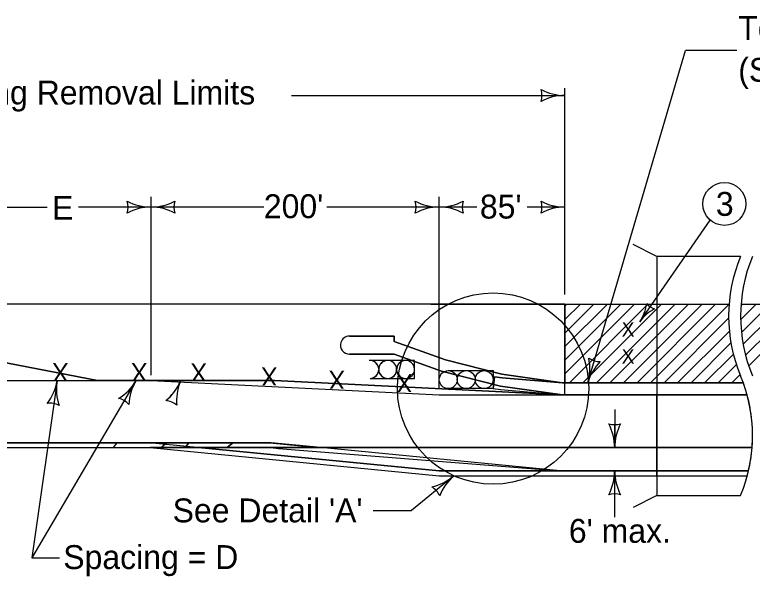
# Model space of a CAD drawing. Extents: x 10133 to 2270741, y 5363 to 1733450.
# Drawn here: x 26474 to 27091, y 6564 to 7034 of the extents above; entities that cross this region are included whole.
import ezdxf

# ---------------------------------------------------------------- set-up
doc = ezdxf.new("R2010")
doc.units = 0
for name, color, linetype in [('dsnNonPlotable', 7, 'Continuous'), ('dsnShtPlotShapeBatchPrint', 7, 'Continuous'), ('dsnStdBlockModified', 7, 'Continuous'), ('dsnStdBorder', 7, 'Continuous'), ('Level 12', 7, 'Continuous'), ('Level 2', 7, 'Continuous')]:
    doc.layers.add(name, color=color, linetype=linetype)

# ---------------------------------------------------------------- blocks, each defined once
blk = doc.blocks.new('LT')
at = {"layer": 'dsnStdBorder'}
for centre, radius, start, end in [((-3.564, 0), 1.642, 342.26665, 17.73335), ((0, 4.25), 4.25, 241.92751, 270), ((0, -4.25), 4.25, 90, 118.07249)]:
    blk.add_arc(centre, radius, start, end, dxfattribs=at)

msp = doc.modelspace()

# ---------------------------------------------------------------- linework, layer by layer
at = {"layer": 'dsnNonPlotable'}
for p, q in [((27011.27, 6831.83), (26991.27, 6841.83)), ((26439.83, 6728.09), (26588.02, 6728.09)), ((26588.02, 6728.09), (26829.07, 6716.09)), ((26932.38, 6726.09), (27083.5, 6726.09)), ((26829.07, 6716.09), (26932.38, 6716.09)), ((27086.67, 6716.09), (26932.38, 6716.09)), ((24557.83, 6675.81), (26586.2, 6675.81)), ((26587.39, 6671.83), (26913.23, 6671.83)), ((26913.23, 6671.83), (27090.89, 6671.83)), ((26829.07, 6652.32), (27087.88, 6652.32)), ((27011.27, 6631.83), (26991.27, 6621.83))]:
    msp.add_line(p, q, dxfattribs=at)
for points in [[(27081.27, 6831.83), (27011.27, 6831.83), (27011.27, 6631.83), (27081.27, 6631.83)], [(26875.5, 6731.07), (26874.23, 6721.23), (26874.23, 6721.23)], [(26875.5, 6731.07), (26881.73, 6730.26), (26932.38, 6726.09)], [(26874.23, 6721.23), (26880.46, 6720.42), (26932.38, 6716.09)]]:
    msp.add_lwpolyline(points, dxfattribs=at)
for centre, start, end in [((27201.27, 6781.83), 157.38014, 202.61987), ((27211.27, 6781.83), 157.38014, 202.61987), ((26961.27, 6681.83), 337.38014, 22.61987)]:
    msp.add_arc(centre, 130, start, end, dxfattribs=at)
at = {"layer": 'dsnShtPlotShapeBatchPrint'}
msp.add_circle((27067.71, 6875.77), 18, dxfattribs=at)
at = {"layer": 'dsnStdBlockModified'}
for p, q in [((26836.72, 6736.23), (26874.23, 6736.23)), ((26874.23, 6736.23), (26874.23, 6721.23)), ((26874.23, 6721.23), (26836.72, 6721.23))]:
    msp.add_line(p, q, dxfattribs=at)
for centre in [(26836.72, 6728.73), (26836.72, 6728.73), (26851.73, 6728.73), (26851.73, 6728.73), (26866.73, 6728.73), (26866.73, 6728.73)]:
    msp.add_circle(centre, 7.5, dxfattribs=at)
at = {"layer": 'dsnStdBorder'}
for p, q in [((26934.34, 6790.27), (26935.89, 6791.83)), ((26934.34, 6778.95), (26947.21, 6791.83)), ((26934.34, 6767.64), (26958.52, 6791.83)), ((26934.34, 6756.33), (26969.84, 6791.83)), ((26934.34, 6745.01), (26981.15, 6791.83)), ((26934.34, 6733.7), (26992.46, 6791.83)), ((26934.34, 6791.83), (26934.34, 6726.09)), ((26938.04, 6726.09), (27003.78, 6791.83)), ((26949.36, 6726.09), (27015.09, 6791.83)), ((26960.67, 6726.09), (27026.4, 6791.83)), ((26971.98, 6726.09), (27037.72, 6791.83)), ((26983.3, 6726.09), (27049.03, 6791.83)), ((26994.61, 6726.09), (27060.34, 6791.83)), ((27045.11, 6787.86), (27049.07, 6791.83)), ((27045.89, 6766.06), (27071.66, 6791.83)), ((27081.31, 6778.85), (27094.29, 6791.83)), ((27081.56, 6790.41), (27082.97, 6791.83)), ((27081.99, 6768.21), (27105.6, 6791.83)), ((27083.41, 6758.33), (27116.91, 6791.83)), ((27085.47, 6749.07), (27128.23, 6791.83)), ((27088.07, 6740.35), (27139.54, 6791.83)), ((27017.24, 6726.09), (27071.28, 6780.14)), ((27028.55, 6726.09), (27071.87, 6769.41)), ((27005.92, 6726.09), (27045.89, 6766.06)), ((27039.87, 6726.09), (27073.21, 6759.44)), ((27051.18, 6726.09), (27075.2, 6750.12)), ((27062.49, 6726.09), (27077.74, 6741.34)), ((27073.81, 6726.09), (27080.77, 6733.05)), ((26829.07, 6652.32), (26586.2, 6675.81))]:
    msp.add_line(p, q, dxfattribs=at)
for centre, radius in [((26874.23, 6721.23), 80), ((26836.72, 6728.73), 7.5), ((26851.73, 6728.73), 7.5), ((26866.73, 6728.73), 7.5)]:
    msp.add_circle(centre, radius, dxfattribs=at)
at = {"layer": 'Level 12'}
for p, q in [((26953.42, 6726.09), (27035.19, 7004.13)), ((27078.03, 7004.13), (27035.19, 7004.13)), ((26934.34, 6799.83), (26934.34, 6972.59)), ((26705.58, 6966.53), (26934.34, 6966.53)), ((26588.02, 6732.52), (26588.02, 6881.62)), ((26829.07, 6720.64), (26829.07, 6881.62)), ((26384.24, 6873.11), (26501.08, 6873.11)), ((26682.49, 6873.11), (26527.28, 6873.11)), ((26829.07, 6873.11), (26735.18, 6873.11)), ((26860.64, 6873.11), (26829.07, 6873.11)), ((26934.34, 6873.11), (26902.77, 6873.11)), ((26996.87, 6777.1), (27055.83, 6862.25)), ((26509.43, 6727.69), (26488.2, 6579.64)), ((26575.4, 6727.69), (26488.2, 6579.64)), ((26975.92, 6703.83), (26975.92, 6671.83)), ((26965.1, 6671.83), (26983.92, 6671.83)), ((26966.11, 6652.32), (26983.92, 6652.32)), ((26975.92, 6613.56), (26975.92, 6652.32)), ((26841.33, 6648.31), (26805.99, 6619.1)), ((26773.99, 6619.1), (26805.99, 6619.1)), ((26488.2, 6579.64), (26511.33, 6579.64))]:
    msp.add_line(p, q, dxfattribs=at)
for centre, radius, start, end in [((26898.7, 6966.53), 16.42, 342.26665, 17.73335), ((26934.34, 7009.03), 42.5, 241.92751, 270), ((26934.34, 6924.03), 42.5, 90, 118.07249), ((26552.38, 6873.11), 16.42, 342.26665, 17.73335), ((26588.02, 6915.61), 42.5, 241.92751, 270), ((26588.02, 6915.61), 42.5, 270, 298.07249), ((26623.65, 6873.11), 16.42, 162.26665, 197.73335), ((26793.43, 6873.11), 16.42, 342.26665, 17.73335), ((26829.07, 6915.61), 42.5, 241.92751, 270), ((26829.07, 6915.61), 42.5, 270, 298.07249), ((26864.71, 6873.11), 16.42, 162.26665, 197.73335), ((26898.7, 6873.11), 16.42, 342.26665, 17.73335), ((26934.34, 6915.61), 42.5, 241.92751, 270), ((26588.02, 6830.61), 42.5, 90, 118.07249), ((26588.02, 6830.61), 42.5, 61.92751, 90), ((26829.07, 6830.61), 42.5, 90, 118.07249), ((26829.07, 6830.61), 42.5, 61.92751, 90), ((26934.34, 6830.61), 42.5, 90, 118.07249), ((26912.65, 6738.08), 42.5, 343.61306, 11.68555), ((26994.2, 6714.1), 42.5, 135.54057, 163.61306), ((26963.48, 6760.28), 16.42, 235.87971, 271.34641), ((26467.49, 6734.6), 42.5, 322.56873, 350.64122), ((26551.36, 6720.78), 42.5, 170.64122, 198.71371), ((26538.78, 6749.25), 42.5, 301.43193, 329.50442), ((26612.02, 6706.12), 42.5, 149.50442, 177.57691), ((26557.31, 6696.98), 16.42, 41.77107, 77.23777), ((26503.63, 6692.53), 16.42, 62.90787, 98.37457), ((26975.92, 6707.46), 16.42, 252.26665, 287.73335), ((26933.42, 6671.83), 42.5, 360, 28.07249), ((27018.42, 6671.83), 42.5, 151.92751, 180), ((26933.42, 6652.32), 42.5, 331.92751, 360), ((27018.42, 6652.32), 42.5, 180, 208.07249), ((26813.42, 6680.36), 42.5, 282.97403, 311.04652), ((26869.24, 6616.25), 42.5, 131.04652, 159.11901), ((26814.45, 6624.91), 16.42, 23.31317, 58.77987), ((26975.92, 6616.69), 16.42, 72.26665, 107.73335)]:
    msp.add_arc(centre, radius, start, end, dxfattribs=at)
at = {"layer": 'Level 2'}
for p, q in [((26822.2, 6791.83), (25991.54, 6791.83)), ((26822.2, 6791.83), (27071.66, 6791.83)), ((27081.66, 6791.83), (27600.09, 6791.83)), ((26934.34, 6767.64), (26934.34, 6778.95)), ((26791.49, 6760.74), (26791.49, 6765.11)), ((26768.85, 6750.1), (26754.1, 6750.1)), ((26754.1, 6750.1), (26768.85, 6750.1)), ((26783.87, 6750.1), (26769.12, 6750.1)), ((26769.12, 6750.1), (26783.87, 6750.1)), ((26791.49, 6750.1), (26784.11, 6750.1)), ((26784.11, 6750.1), (26791.49, 6750.1)), ((26441.61, 6747.61), (26543.14, 6728.09)), ((26543.14, 6728.09), (26441.61, 6747.61)), ((26785.62, 6744.76), (26771.01, 6744.76)), ((26800.63, 6744.76), (26785.62, 6744.76)), ((26808.52, 6744.76), (26800.63, 6744.76)), ((26808.52, 6737.65), (26808.52, 6744.76)), ((26934.34, 6733.7), (26934.34, 6745.01)), ((26808.52, 6729.76), (26808.52, 6737.26)), ((26934.34, 6726.09), (26934.34, 6733.7)), ((26543.14, 6728.09), (26658.52, 6728.09)), ((26691.32, 6728.09), (26543.14, 6728.09)), ((26612.73, 6727.69), (26612.13, 6726.15)), ((26658.53, 6728.09), (26691.32, 6728.09)), ((26691.32, 6728.09), (26932.38, 6716.09)), ((26932.38, 6716.09), (26691.32, 6728.09)), ((26771.4, 6729.76), (26785.97, 6729.76)), ((26786.41, 6729.76), (26801.41, 6729.76)), ((26801.41, 6729.76), (26808.52, 6729.76)), ((26875.5, 6731.07), (26874.23, 6721.23)), ((27083.5, 6726.09), (26932.38, 6726.09)), ((26934.34, 6715.99), (26934.34, 6726.09)), ((26932.38, 6716.09), (27086.67, 6716.09)), ((27011.27, 6716.09), (26932.38, 6716.09)), ((26932.38, 6716.09), (26934.34, 6715.99)), ((27086.67, 6716.09), (27011.27, 6716.09)), ((27011.27, 6716.09), (27011.27, 6671.83)), ((27011.27, 6671.83), (27011.27, 6716.09)), ((26975.92, 6671.83), (26975.92, 6691.05)), ((26380.14, 6671.83), (26616.66, 6671.83)), ((26619.64, 6675.83), (26383.38, 6675.83)), ((26559.31, 6675.83), (26556.38, 6671.83)), ((26556.38, 6671.83), (26596.12, 6671.83)), ((26601.17, 6675.83), (26559.31, 6675.83)), ((26627.68, 6671.83), (26587.39, 6671.83)), ((26587.39, 6671.83), (26829.07, 6648.32)), ((26587.39, 6671.83), (26829.07, 6648.32)), ((26596.12, 6671.83), (26601.17, 6675.83)), ((26616.66, 6671.83), (26619.64, 6675.83)), ((26619.64, 6675.83), (26616.66, 6671.83)), ((26616.66, 6671.83), (26651.62, 6671.83)), ((26656.46, 6675.83), (26619.64, 6675.83)), ((26829.07, 6652.32), (26627.68, 6671.83)), ((26913.23, 6671.83), (26627.68, 6671.83)), ((26627.68, 6671.83), (26829.07, 6652.32)), ((26656.46, 6675.83), (26651.62, 6671.83)), ((26651.62, 6671.83), (26656.46, 6675.83)), ((26687.23, 6675.81), (26728.39, 6671.83)), ((26729.75, 6671.83), (26688.43, 6671.83)), ((26688.43, 6671.83), (26694.74, 6671.21)), ((26729.75, 6671.83), (26688.63, 6675.83)), ((26694.74, 6671.21), (26930.29, 6652.32)), ((26728.39, 6671.83), (26729.75, 6671.83)), ((26930.29, 6652.32), (26729.75, 6671.83)), ((26729.75, 6671.83), (26913.23, 6671.83)), ((27090.89, 6671.83), (27011.27, 6671.83)), ((27011.27, 6671.83), (27011.27, 6652.32)), ((27011.27, 6671.83), (27090.89, 6671.83)), ((27011.27, 6652.32), (27011.27, 6671.83)), ((26975.92, 6652.32), (26829.07, 6652.32)), ((26829.07, 6652.32), (26966.11, 6652.32)), ((26930.3, 6652.32), (27087.88, 6652.32)), ((26966.11, 6652.32), (26975.92, 6652.32)), ((26983.92, 6652.32), (26975.92, 6652.32)), ((26975.92, 6652.32), (26983.92, 6652.32)), ((27011.27, 6652.32), (26983.92, 6652.32)), ((26983.92, 6652.32), (27011.27, 6652.32)), ((27011.27, 6652.32), (27087.88, 6652.32)), ((27011.27, 6648.32), (27011.27, 6652.32)), ((27011.27, 6652.32), (27011.27, 6648.32)), ((27061.54, 6652.32), (27087.88, 6652.32)), ((26829.07, 6648.32), (27086.88, 6648.32)), ((26829.07, 6648.32), (26975.73, 6648.32)), ((26976.11, 6648.32), (27011.27, 6648.32)), ((27060.54, 6648.32), (27086.88, 6648.32))]:
    msp.add_line(p, q, dxfattribs=at)
for points in [[(26934.34, 6791.83), (26894.01, 6791.83), (26822.2, 6791.83)], [(26934.34, 6778.95), (26934.34, 6790.27), (26934.34, 6791.83)], [(26753.98, 6765.11), (26753.98, 6765.11), (26783.98, 6765.11), (26784.01, 6765.11), (26791.49, 6765.11)], [(26791.49, 6765.11), (26783.98, 6765.11), (26753.98, 6765.11)], [(26791.49, 6765.11), (26791.49, 6760.74), (26791.49, 6760.74)], [(26934.34, 6745.01), (26934.34, 6756.33), (26934.34, 6767.64)], [(26791.49, 6760.74), (26834.35, 6745.15), (26881.62, 6733.22), (26932.38, 6726.09), (26934.34, 6726.09)], [(26934.34, 6726.09), (26932.38, 6726.09), (26881.62, 6733.22), (26834.35, 6745.15), (26791.49, 6760.74)], [(26932.38, 6716.09), (26880.44, 6723.35), (26830.93, 6735.75), (26791.49, 6750.1)], [(26791.49, 6750.1), (26830.93, 6735.75), (26880.44, 6723.35), (26932.38, 6716.09)], [(26785.62, 6744.75), (26785.62, 6744.76)], [(26785.62, 6744.76), (26785.62, 6744.75)], [(26800.63, 6744.75), (26800.63, 6744.76)], [(26800.63, 6744.76), (26800.63, 6744.75)], [(26778.5, 6737.65), (26778.52, 6737.65)], [(26793.51, 6737.65), (26793.53, 6737.65)], [(26808.51, 6737.65), (26808.52, 6737.65)], [(26612.13, 6726.15), (26612.07, 6726.18)], [(26658.52, 6728.09), (26658.53, 6728.09), (26658.77, 6728.43)], [(26771.4, 6729.77), (26771.4, 6729.76)], [(26786.41, 6729.77), (26786.41, 6729.76)], [(26801.41, 6729.77), (26801.41, 6729.76)], [(26801.41, 6729.76), (26801.41, 6729.77)], [(26932.38, 6726.09), (26881.73, 6730.26), (26875.5, 6731.07)], [(26874.23, 6721.23), (26880.46, 6720.42), (26932.03, 6716.12), (26932.38, 6716.09)], [(26932.38, 6716.09), (26932.38, 6716.09)], [(26383.36, 6675.81), (26592.16, 6675.81), (26687.23, 6675.81)], [(26651.62, 6671.83), (26688.43, 6671.83), (26729.75, 6671.83)], [(26688.63, 6675.83), (26687.67, 6675.83), (26656.46, 6675.83)], [(27011.27, 6671.83), (26983.92, 6671.83), (26975.92, 6671.83), (26965.1, 6671.83), (26913.23, 6671.83)], [(26913.23, 6671.83), (26965.1, 6671.83), (26975.92, 6671.83)], [(26975.92, 6671.83), (26983.92, 6671.83), (27011.27, 6671.83)], [(27087.88, 6652.32), (27061.54, 6652.32), (27011.27, 6652.32)], [(27011.27, 6648.32), (27060.54, 6648.32), (27086.88, 6648.32)]]:
    msp.add_lwpolyline(points, dxfattribs=at)
for centre, radius, start, end in [((26753.98, 6757.6), 7.5, 90, 163.05255), ((26753.98, 6757.6), 7.5, 90, 163.05255), ((26753.98, 6757.6), 7.5, 163.04978, 270.9263), ((26753.98, 6757.6), 7.5, 163.04978, 270.9263), ((26768.99, 6757.6), 7.5, 268.97742, 271.02258), ((26768.99, 6757.6), 7.5, 268.97742, 271.02258), ((26783.99, 6757.6), 7.5, 269.06509, 270.93491), ((26783.99, 6757.6), 7.5, 269.06509, 270.93491), ((26771.01, 6737.26), 7.5, 3.00007, 92.99993), ((26771.01, 6737.26), 7.5, 2.99574, 90), ((26786.01, 6737.26), 7.5, 93.04482, 93), ((26786.01, 6737.26), 7.5, 93.04172, 177.01242), ((26786.01, 6737.26), 7.5, 2.99574, 92.9969), ((26801.02, 6737.26), 7.5, 93.00604, 182.99396), ((26801.02, 6737.26), 7.5, 92.9969, 177.01242), ((26801.01, 6737.25), 7.51, 3.1005, 92.8995), ((26801.02, 6737.26), 7.5, 2.99593, 92.9969), ((26801.02, 6737.26), 7.5, 272.99981, 3.00019), ((26770.99, 6737.31), 7.55, 273.14031, 356.68109), ((26771.01, 6737.26), 7.5, 273.00246, 317.97075), ((26770.99, 6737.31), 7.55, 317.82762, 356.66631), ((26786.01, 6737.26), 7.5, 183.01314, 269.67748), ((26785.99, 6737.31), 7.55, 273.14439, 356.67701), ((26786.01, 6737.26), 7.5, 272.99983, 319.05414), ((26785.99, 6737.31), 7.55, 318.90204, 356.5996), ((26801.02, 6737.26), 7.5, 182.99578, 273.00422), ((26801.02, 6737.26), 7.5, 183.08128, 273.00246), ((26801.02, 6737.26), 7.5, 273.00246, 0), ((26573.54, 6744.12), 42.5, 309.18469, 337.23958), ((26573.54, 6744.12), 42.5, 309.18469, 335.03167), ((26651.93, 6711.26), 42.5, 159.48606, 185.32967), ((26651.93, 6711.26), 42.5, 159.48606, 185.32967), ((26651.93, 6711.26), 42.5, 157.25718, 157.27479), ((26693.11, 6703.39), 42.5, 143.91819, 144.46106), ((26693.11, 6703.39), 42.5, 143.90058, 143.90114), ((26624.44, 6753.47), 42.5, 323.88298, 323.90058), ((26961.27, 6681.83), 130, 15.28231, 19.90723), ((26961.27, 6681.83), 130, 355.58827, 15.28231), ((26598.96, 6694.82), 16.42, 49.52383, 84.99053), ((26598.96, 6694.82), 16.42, 49.52383, 84.99053), ((26975.92, 6707.46), 16.42, 252.26665, 270), ((26933.42, 6671.83), 42.5, 0.0176, 28.07249), ((27018.42, 6671.83), 42.5, 179.9824, 180), ((26961.27, 6681.83), 130, 346.88165, 355.58827), ((26933.42, 6652.32), 42.5, 354.59945, 360), ((26933.42, 6652.32), 42.5, 359.9824, 360), ((27018.42, 6652.32), 42.5, 180.0176, 185.40055), ((26961.27, 6681.83), 130, 345.06444, 346.88165)]:
    msp.add_arc(centre, radius, start, end, dxfattribs=at)

# ---------------------------------------------------------------- block references
at = {"layer": 'Level 12', "xscale": 7.999600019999, "yscale": 7.999200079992, "rotation": -124.70293665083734}
msp.add_blockref('LT', (26996.87, 6777.1), dxfattribs=at)

# ---------------------------------------------------------------- texts
at = {"layer": 'dsnShtPlotShapeBatchPrint'}
msp.add_text('3', height=20, dxfattribs=at).set_placement((27060.57, 6865.77))
at = {"layer": 'dsnStdBorder'}
for p in [(26981.79, 6764.75), (26981.79, 6742.1)]:
    msp.add_text('X', height=12, dxfattribs=at).set_placement(p)
for p in [(26518.93, 6742.53), (26584.89, 6742.53), (26634.64, 6742.34), (26693.67, 6739), (26750.19, 6736.2), (26806.72, 6733.39)]:
    msp.add_text('X', height=15, rotation=180, dxfattribs=at).set_placement(p)
at = {"layer": 'Level 12'}
for s, p in [('Temporary Barrier Rail', (27079.31, 7012.98)), ('(See Typical 8210)', (27079.31, 6977.98)), ('Pavement Marking Removal Limits', (26261.97, 6958.94)), ('E', (26505.34, 6862.5)), ("200'", (26682.41, 6863.82)), ("85'", (26863.16, 6863.5)), ("See Detail 'A'", (26606.1, 6609.28)), ("6' max.", (26937.6, 6592.16)), ('Spacing = D', (26514.6, 6570.22))]:
    msp.add_text(s, height=20, dxfattribs=at).set_placement(p)

doc.saveas('drawing.dxf')
